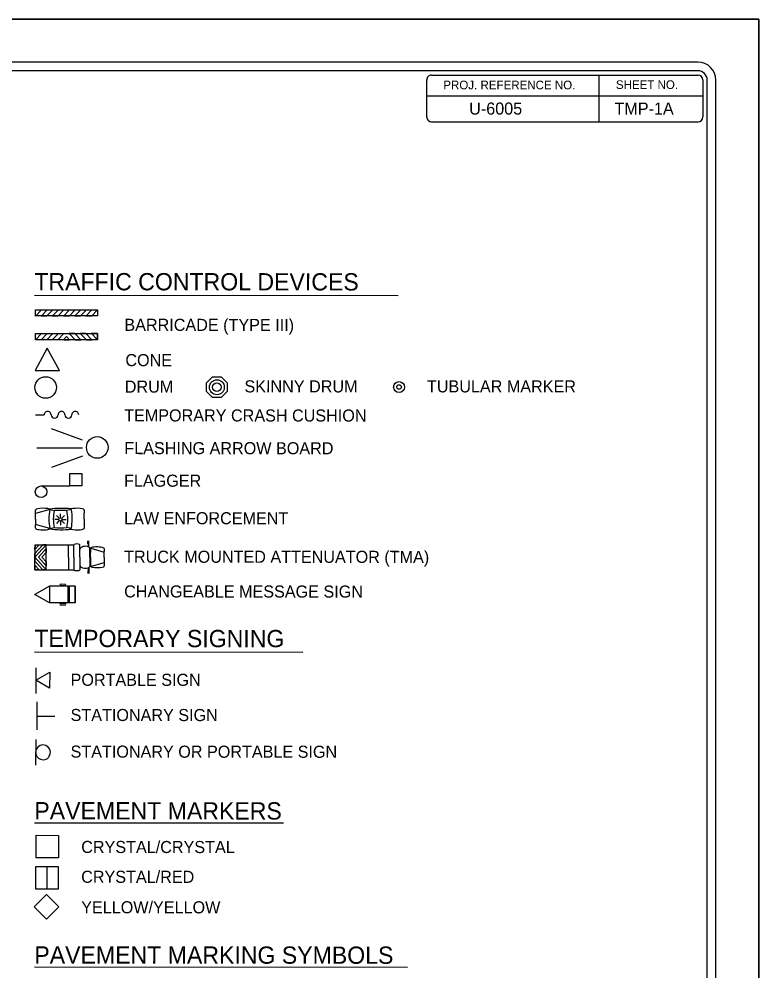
# Model space of a CAD drawing. Extents: x 1403867 to 1405555, y 486423 to 487523.
# Drawn here: x 1405127 to 1405555, y 486971 to 487523 of the extents above; entities that cross this region are included whole.
import ezdxf

# ---------------------------------------------------------------- set-up
doc = ezdxf.new("R2010")
doc.units = 0
for name, color, linetype in [('DEV BORDER CELL', 7, 'Continuous'), ('MARK YELLOW RPM CELL', 7, 'Continuous'), ('Sheet Plot Border Outside CELL', 7, 'Continuous')]:
    doc.layers.add(name, color=color, linetype=linetype)

msp = doc.modelspace()

# ---------------------------------------------------------------- linework, layer by layer
at = {"layer": 'DEV BORDER CELL'}
for p, q in [((1405520.08, 487497.72), (1404040.64, 487497.72)), ((1405520.08, 487492.72), (1404608.13, 487492.72)), ((1405362.86, 487465.99), (1405362.86, 487487.49)), ((1405365.65, 487490.22), (1405520.09, 487490.22)), ((1405462.86, 487478.22), (1405462.86, 487490.22)), ((1405522.86, 487487.44), (1405522.86, 487485.29)), ((1405522.86, 487485.29), (1405522.86, 487466.01)), ((1405525.36, 486458), (1405525.36, 487487.44)), ((1405530.36, 486458), (1405530.36, 487487.44)), ((1405362.86, 487478.22), (1405522.86, 487478.22)), ((1405462.86, 487463.22), (1405462.86, 487478.22)), ((1405365.65, 487463.22), (1405520.08, 487463.22)), ((1405135.49, 487362.76), (1405346.38, 487362.61)), ((1405136.16, 487350.69), (1405136.16, 487354.3)), ((1405136.16, 487354.3), (1405139.7, 487354.3)), ((1405139.7, 487354.3), (1405136.16, 487350.69)), ((1405136.16, 487354.3), (1405172.14, 487354.3)), ((1405136.16, 487350.75), (1405136.16, 487354.3)), ((1405139.39, 487350.69), (1405142.94, 487354.3)), ((1405146.18, 487354.3), (1405142.63, 487350.69)), ((1405142.94, 487354.3), (1405146.18, 487354.3)), ((1405145.87, 487350.69), (1405149.41, 487354.3)), ((1405152.65, 487354.3), (1405149.11, 487350.69)), ((1405149.41, 487354.3), (1405152.65, 487354.3)), ((1405152.34, 487350.69), (1405155.89, 487354.3)), ((1405159.13, 487354.3), (1405155.58, 487350.69)), ((1405155.89, 487354.3), (1405159.13, 487354.3)), ((1405158.82, 487350.69), (1405162.42, 487354.3)), ((1405165.66, 487354.3), (1405162.06, 487350.69)), ((1405162.42, 487354.3), (1405165.66, 487354.3)), ((1405165.3, 487350.69), (1405168.9, 487354.3)), ((1405172.14, 487354.3), (1405168.53, 487350.69)), ((1405168.9, 487354.3), (1405172.14, 487354.3)), ((1405172.14, 487354.3), (1405172.14, 487350.75)), ((1405172.14, 487350.75), (1405136.16, 487350.75)), ((1405142.63, 487350.69), (1405139.39, 487350.69)), ((1405149.11, 487350.69), (1405145.87, 487350.69)), ((1405155.58, 487350.69), (1405152.34, 487350.69)), ((1405162.06, 487350.69), (1405158.82, 487350.69)), ((1405168.53, 487350.69), (1405165.3, 487350.69)), ((1405136.16, 487336.98), (1405136.16, 487340.58)), ((1405136.16, 487340.58), (1405139.71, 487340.58)), ((1405139.71, 487340.58), (1405136.16, 487336.98)), ((1405136.16, 487340.58), (1405172.14, 487340.58)), ((1405136.16, 487336.98), (1405136.16, 487340.58)), ((1405172.14, 487336.98), (1405136.16, 487336.98)), ((1405139.4, 487336.98), (1405142.94, 487340.58)), ((1405142.64, 487336.98), (1405139.4, 487336.98)), ((1405146.18, 487340.58), (1405142.64, 487336.98)), ((1405142.94, 487340.58), (1405146.18, 487340.58)), ((1405145.87, 487336.98), (1405149.42, 487340.58)), ((1405149.11, 487336.98), (1405145.87, 487336.98)), ((1405152.65, 487340.58), (1405149.11, 487336.98)), ((1405149.42, 487340.58), (1405152.65, 487340.58)), ((1405152.35, 487336.98), (1405154.15, 487338.81)), ((1405155.59, 487336.98), (1405152.35, 487336.98)), ((1405152.71, 487336.98), (1405155.95, 487336.98)), ((1405154.15, 487338.81), (1405155.95, 487336.98)), ((1405158.88, 487340.58), (1405155.65, 487340.58)), ((1405155.65, 487340.58), (1405159.19, 487336.98)), ((1405162.43, 487336.98), (1405158.88, 487340.58)), ((1405159.19, 487336.98), (1405162.43, 487336.98)), ((1405165.36, 487340.58), (1405162.12, 487340.58)), ((1405162.12, 487340.58), (1405165.66, 487336.98)), ((1405168.9, 487336.98), (1405165.36, 487340.58)), ((1405165.66, 487336.98), (1405168.9, 487336.98)), ((1405172.14, 487340.58), (1405168.59, 487340.58)), ((1405168.59, 487340.58), (1405172.14, 487336.98)), ((1405172.14, 487340.58), (1405172.14, 487336.98)), ((1405172.14, 487336.98), (1405172.14, 487340.58)), ((1405136.2, 487293.47), (1405141.2, 487293.47)), ((1405163.46, 487278.75), (1405145.42, 487285.33)), ((1405163.45, 487274.14), (1405136.91, 487274.16)), ((1405163.45, 487269.54), (1405145.4, 487262.98)), ((1405139.38, 487252.25), (1405156.06, 487252.24)), ((1405144.47, 487238.54), (1405136.25, 487236.3)), ((1405144.47, 487238.54), (1405147.01, 487237.99)), ((1405156.88, 487238.53), (1405154.34, 487237.98)), ((1405156.16, 487238.68), (1405156.16, 487238.38)), ((1405136.24, 487233.09), (1405136.25, 487236.3)), ((1405136.24, 487233.09), (1405136.24, 487229.86)), ((1405149.31, 487232.88), (1405147.29, 487232.88)), ((1405149.68, 487231.96), (1405148.25, 487230.54)), ((1405149.69, 487233.79), (1405148.26, 487235.22)), ((1405150.61, 487234.17), (1405150.61, 487236.19)), ((1405151.51, 487231.95), (1405152.94, 487230.53)), ((1405151.52, 487233.78), (1405152.95, 487235.21)), ((1405151.89, 487232.87), (1405153.91, 487232.87)), ((1405164.35, 487233.07), (1405164.35, 487236.28)), ((1405164.35, 487233.07), (1405164.35, 487229.84)), ((1405144.46, 487227.6), (1405136.24, 487229.86)), ((1405144.46, 487227.6), (1405147, 487228.15)), ((1405150.6, 487231.58), (1405150.59, 487229.56)), ((1405156.88, 487227.59), (1405154.33, 487228.14)), ((1405156.15, 487227.77), (1405156.15, 487227.46)), ((1405156.15, 487227.77), (1405156.15, 487227.46)), ((1405135.87, 487203.65), (1405135.88, 487218.2)), ((1405135.88, 487218.2), (1405135.87, 487215.43)), ((1405138.35, 487218.2), (1405135.87, 487215.43)), ((1405135.87, 487213.18), (1405140.38, 487218.2)), ((1405142.33, 487218.2), (1405135.87, 487210.93)), ((1405135.88, 487218.2), (1405158.38, 487218.19)), ((1405135.88, 487218.2), (1405138.35, 487218.2)), ((1405137.9, 487210.93), (1405142.32, 487215.95)), ((1405140.38, 487218.2), (1405142.33, 487218.2)), ((1405142.32, 487203.65), (1405142.33, 487218.2)), ((1405142.32, 487215.95), (1405142.32, 487213.7)), ((1405155.3, 487210.92), (1405155.3, 487218.19)), ((1405158.37, 487210.91), (1405158.38, 487218.19)), ((1405161.82, 487210.91), (1405161.83, 487218.19)), ((1405166.48, 487218.63), (1405166.48, 487220.43)), ((1405166.78, 487216.91), (1405166.78, 487220.43)), ((1405167, 487216.91), (1405167, 487220.43)), ((1405167.6, 487210.91), (1405167.6, 487216.16)), ((1405168.12, 487210.91), (1405168.13, 487216.16)), ((1405168.13, 487216.16), (1405176, 487213.98)), ((1405135.87, 487210.93), (1405135.87, 487213.18)), ((1405135.87, 487210.93), (1405142.32, 487203.65)), ((1405135.87, 487208.75), (1405135.87, 487210.93)), ((1405142.32, 487205.98), (1405137.9, 487210.93)), ((1405142.32, 487213.7), (1405139.85, 487210.93)), ((1405139.92, 487210.93), (1405142.32, 487208.23)), ((1405155.3, 487210.92), (1405155.29, 487203.64)), ((1405158.37, 487210.91), (1405158.37, 487203.64)), ((1405161.82, 487210.91), (1405161.82, 487203.64)), ((1405167.6, 487210.91), (1405167.59, 487205.66)), ((1405168.12, 487210.91), (1405168.12, 487205.66)), ((1405176, 487210.9), (1405175.99, 487207.83)), ((1405176, 487210.9), (1405176, 487213.98)), ((1405140.37, 487203.65), (1405135.87, 487208.75)), ((1405135.87, 487206.43), (1405135.87, 487203.65)), ((1405138.34, 487203.65), (1405135.87, 487206.43)), ((1405142.32, 487208.23), (1405142.32, 487205.98)), ((1405166.77, 487204.91), (1405166.76, 487201.46)), ((1405166.99, 487204.91), (1405166.99, 487201.46)), ((1405168.12, 487205.66), (1405175.99, 487207.83)), ((1405135.87, 487203.65), (1405158.37, 487203.64)), ((1405135.87, 487203.65), (1405138.34, 487203.65)), ((1405142.32, 487203.65), (1405140.37, 487203.65)), ((1405166.47, 487203.18), (1405166.46, 487201.46)), ((1405144.19, 487194.19), (1405135.78, 487189.35)), ((1405144.19, 487194.19), (1405144.18, 487184.49)), ((1405159.21, 487194.18), (1405144.19, 487194.19)), ((1405153.54, 487195.26), (1405150.44, 487195.27)), ((1405153.54, 487194.38), (1405150.44, 487194.38)), ((1405154.89, 487194.19), (1405154.89, 487184.48)), ((1405155.7, 487194.19), (1405155.69, 487184.48)), ((1405159.21, 487194.19), (1405159.2, 487184.48)), ((1405159.2, 487184.47), (1405159.21, 487194.18)), ((1405144.18, 487184.49), (1405135.78, 487189.35)), ((1405159.2, 487184.48), (1405144.18, 487184.49)), ((1405153.53, 487184.18), (1405150.43, 487184.18)), ((1405153.53, 487183.26), (1405150.43, 487183.26)), ((1405135.49, 487156.07), (1405291.16, 487155.96)), ((1405136.28, 487146.97), (1405136.27, 487132.12)), ((1405136.27, 487139.7), (1405144.38, 487144.34)), ((1405144.38, 487144.34), (1405144.37, 487135.04)), ((1405144.37, 487135.04), (1405136.27, 487139.7)), ((1405136.9, 487127.11), (1405136.89, 487110.91)), ((1405136.89, 487118.94), (1405147.39, 487118.94)), ((1405136.27, 487105.37), (1405136.26, 487090.52)), ((1405135.49, 487057.19), (1405279.87, 487057.09)), ((1405135.49, 486973.66), (1405351.68, 486973.51))]:
    msp.add_line(p, q, dxfattribs=at)
for points in [[(1405142.91, 487332.03), (1405135.92, 487319.06), (1405150, 487319.11)], [(1405235.25, 487306.96), (1405235.25, 487311.94), (1405238.77, 487315.46), (1405243.75, 487315.45), (1405247.26, 487311.92), (1405247.26, 487306.94), (1405243.74, 487303.42), (1405238.76, 487303.43)], [(1405156.06, 487252.24), (1405156.07, 487259.5), (1405163.03, 487259.5), (1405163.02, 487252.24)], [(1405135.87, 487215.43), (1405135.88, 487218.2), (1405138.35, 487218.2)], [(1405140.38, 487218.2), (1405135.87, 487213.18), (1405135.87, 487208.75), (1405140.37, 487203.65), (1405142.32, 487203.65), (1405135.87, 487210.93), (1405142.33, 487218.2)], [(1405142.32, 487205.98), (1405137.9, 487210.93), (1405142.32, 487215.95), (1405142.32, 487213.7), (1405139.92, 487210.93), (1405142.32, 487208.23)], [(1405135.87, 487206.43), (1405138.34, 487203.65), (1405135.87, 487203.65)], [(1405142.85, 487031.73), (1405149.35, 487031.73), (1405149.35, 487018.73), (1405142.85, 487018.74)], [(1405142.56, 487001.35), (1405135.45, 487008.46), (1405142.56, 487015.57), (1405149.67, 487008.46)]]:
    msp.add_lwpolyline(points, close=True, dxfattribs=at)
for points in [[(1405136.52, 487049.87), (1405149.52, 487049.86), (1405149.52, 487036.87), (1405136.52, 487036.87), (1405136.52, 487049.87)], [(1405136.35, 487031.73), (1405149.35, 487031.73), (1405149.35, 487018.73), (1405136.35, 487018.73), (1405136.35, 487031.73)]]:
    msp.add_lwpolyline(points, dxfattribs=at)
for centre, radius in [((1405142.06, 487309.29), 6.25), ((1405241.25, 487309.44), 4.31), ((1405241.25, 487309.44), 2.5), ((1405346.82, 487309.55), 3.13), ((1405346.82, 487309.55), 1.33), ((1405171.95, 487274.56), 6.25), ((1405139.38, 487248.86), 3.37), ((1405150.6, 487232.87), 1.01), ((1405135.7, 487189.36), 0.0857)]:
    msp.add_circle(centre, radius, dxfattribs=at)
for centre, radius, start, end in [((1405520.08, 487487.44), 10.29, 0.0001, 89.9995), ((1405520.08, 487487.44), 5.29, 0.0001, 89.9995), ((1405365.65, 487487.44), 2.79, 90.0005, 181.1644), ((1405520.08, 487487.44), 2.79, 0.0001, 89.9995), ((1405365.65, 487466.01), 2.79, 180.0001, 270.0005), ((1405520.08, 487466.01), 2.79, 270.0005, 359.9999), ((1405143.21, 487293.47), 2, 359.9598, 179.9598), ((1405147.21, 487293.46), 2, 179.9598, 359.9598), ((1405151.21, 487293.46), 2, 359.9598, 179.9598), ((1405155.21, 487293.46), 2, 179.9598, 359.9598), ((1405159.21, 487293.46), 2, 359.9598, 179.9598), ((1405138.27, 487237.36), 2.28, 151.8399, 208.0797), ((1405169.82, 487233.05), 25.94, 167.7922, 192.1274), ((1405151.51, 487175.53), 63.71, 85.1127, 96.5547), ((1405169.82, 487233.05), 23.34, 167.7922, 192.1274), ((1405150.64, 487186.62), 51.49, 85.8778, 94.0418), ((1405131.52, 487233.08), 23.34, 347.7922, 12.1274), ((1405131.52, 487233.08), 25.94, 347.7922, 12.1274), ((1405162.33, 487237.34), 2.28, 331.8399, 28.0797), ((1405138.27, 487228.79), 2.28, 151.8399, 208.0797), ((1405151.59, 487290.62), 63.71, 263.3649, 274.6973), ((1405150.71, 487281.92), 53.89, 266.0598, 273.8598), ((1405162.32, 487228.77), 2.28, 331.8399, 28.0797), ((1405174.06, 487215.03), 2.18, 331.8399, 28.0797), ((1405174.05, 487206.8), 2.18, 331.8399, 28.0797), ((1405151, 487194.82), 0.717, 142.0481, 217.8715), ((1405152.97, 487194.82), 0.717, 322.0481, 37.8715), ((1405151, 487183.74), 0.717, 142.0481, 217.8715), ((1405152.97, 487183.74), 0.717, 322.0481, 37.8715), ((1405140.54, 487097.94), 4.28, 182.9426, 179.7758)]:
    msp.add_arc(centre, radius, start, end, dxfattribs=at)
for centre, major_axis, ratio, start_param, end_param in [((1405140.37, 487238.48), (-4.1, -0.04), 0.2034, 3.141593, 6.283185), ((1405160.24, 487238.47), (4.1, -0.05), 0.2034, 0, 2.945373), ((1405140.36, 487227.66), (-4.1, 0.05), 0.2034, 0, 3.141593), ((1405160.23, 487227.65), (4.1, 0.04), 0.2034, 3.331712, 6.283185), ((1405160.13, 487218.19), (1.73, 0), 0.269913, 0, 3.141593), ((1405164.74, 487215.8), (2.89, 0.36), 0.503092, 0, 3.141593), ((1405172.05, 487216.11), (3.94, -0.05), 0.2034, 0, 3.141593), ((1405164.73, 487206.04), (2.89, -0.36), 0.503092, 3.141593, 6.283185), ((1405172.04, 487205.72), (3.94, 0.04), 0.2034, 3.141593, 6.283185), ((1405160.12, 487203.65), (1.73, 0), 0.269913, 3.141593, 6.283185)]:
    msp.add_ellipse(centre, major_axis=major_axis, ratio=ratio, start_param=start_param, end_param=end_param, dxfattribs=at)
at = {"layer": 'MARK YELLOW RPM CELL'}
msp.add_lwpolyline([(1405142.56, 487001.35), (1405149.67, 487008.46), (1405142.56, 487015.57), (1405135.45, 487008.46)], close=True, dxfattribs=at)
msp.add_lwpolyline([(1405142.56, 487001.35), (1405149.67, 487008.46), (1405142.56, 487015.57), (1405135.45, 487008.46)], close=True, dxfattribs=at)
at = {"layer": 'Sheet Plot Border Outside CELL'}
for points in [[(1403867.36, 486422.72), (1403867.36, 487522.72), (1405555.36, 487522.72), (1405555.36, 486422.72)], [(1403867.36, 487522.72), (1405555.36, 487522.72), (1405555.36, 486422.72), (1403867.36, 486422.72)], [(1403867.36, 486422.72), (1405555.36, 486422.72), (1405555.36, 487522.72), (1403867.36, 487522.72)]]:
    msp.add_lwpolyline(points, close=True, dxfattribs=at)

# ---------------------------------------------------------------- texts
at = {"layer": 'DEV BORDER CELL'}
for s, height, rotation, p in [('PROJ. REFERENCE NO.', 4.9992, 0.0006, (1405372.46, 487482.02)), ('SHEET NO.', 4.999, 0.0006, (1405472.46, 487482.22)), ('TRAFFIC CONTROL DEVICES', 10, 359.9598, (1405135.49, 487365.61)), ('BARRICADE (TYPE III)', 7, 359.9598, (1405187.67, 487342.1)), ('CONE', 7, 359.9598, (1405188.24, 487321.65)), ('DRUM', 7, 359.9598, (1405187.91, 487306.3)), ('SKINNY DRUM', 7, 359.9598, (1405257.24, 487306.45)), ('TUBULAR MARKER', 7, 359.9598, (1405362.99, 487306.45)), ('TEMPORARY CRASH CUSHION', 7, 359.9598, (1405187.54, 487289.64)), ('FLASHING ARROW BOARD', 7, 359.9598, (1405187.63, 487270.67)), ('FLAGGER', 7, 359.9598, (1405187.47, 487251.83)), ('LAW ENFORCEMENT', 7, 359.9598, (1405187.48, 487230.1)), ('TRUCK MOUNTED ATTENUATOR (TMA)', 7, 359.9598, (1405187.5, 487207.78)), ('CHANGEABLE MESSAGE SIGN', 7, 359.9598, (1405187.52, 487187.67)), ('TEMPORARY SIGNING', 10, 359.9598, (1405135.49, 487158.93)), ('PORTABLE SIGN', 7, 359.9598, (1405156.49, 487136.48)), ('STATIONARY SIGN', 7, 359.9598, (1405156.5, 487116.1)), ('STATIONARY OR PORTABLE SIGN', 7, 359.9598, (1405156.48, 487094.88)), ('PAVEMENT MARKERS', 10, 359.9598, (1405135.49, 487059.12)), ('CRYSTAL/CRYSTAL', 7, 359.9598, (1405162.66, 487039.64)), ('CRYSTAL/RED', 7, 359.9598, (1405162.63, 487022.37)), ('YELLOW/YELLOW', 7, 359.9598, (1405162.65, 487004.72)), ('PAVEMENT MARKING SYMBOLS', 10, 359.9598, (1405135.49, 486975.59))]:
    msp.add_text(s, height=height, rotation=rotation, dxfattribs=at).set_placement(p)
for s, p in [('U-6005', (1405387.45, 487467.36)), ('TMP-1A ', (1405471.64, 487467.36))]:
    msp.add_text(s, height=7, dxfattribs=at).set_placement(p)

doc.saveas('drawing.dxf')
